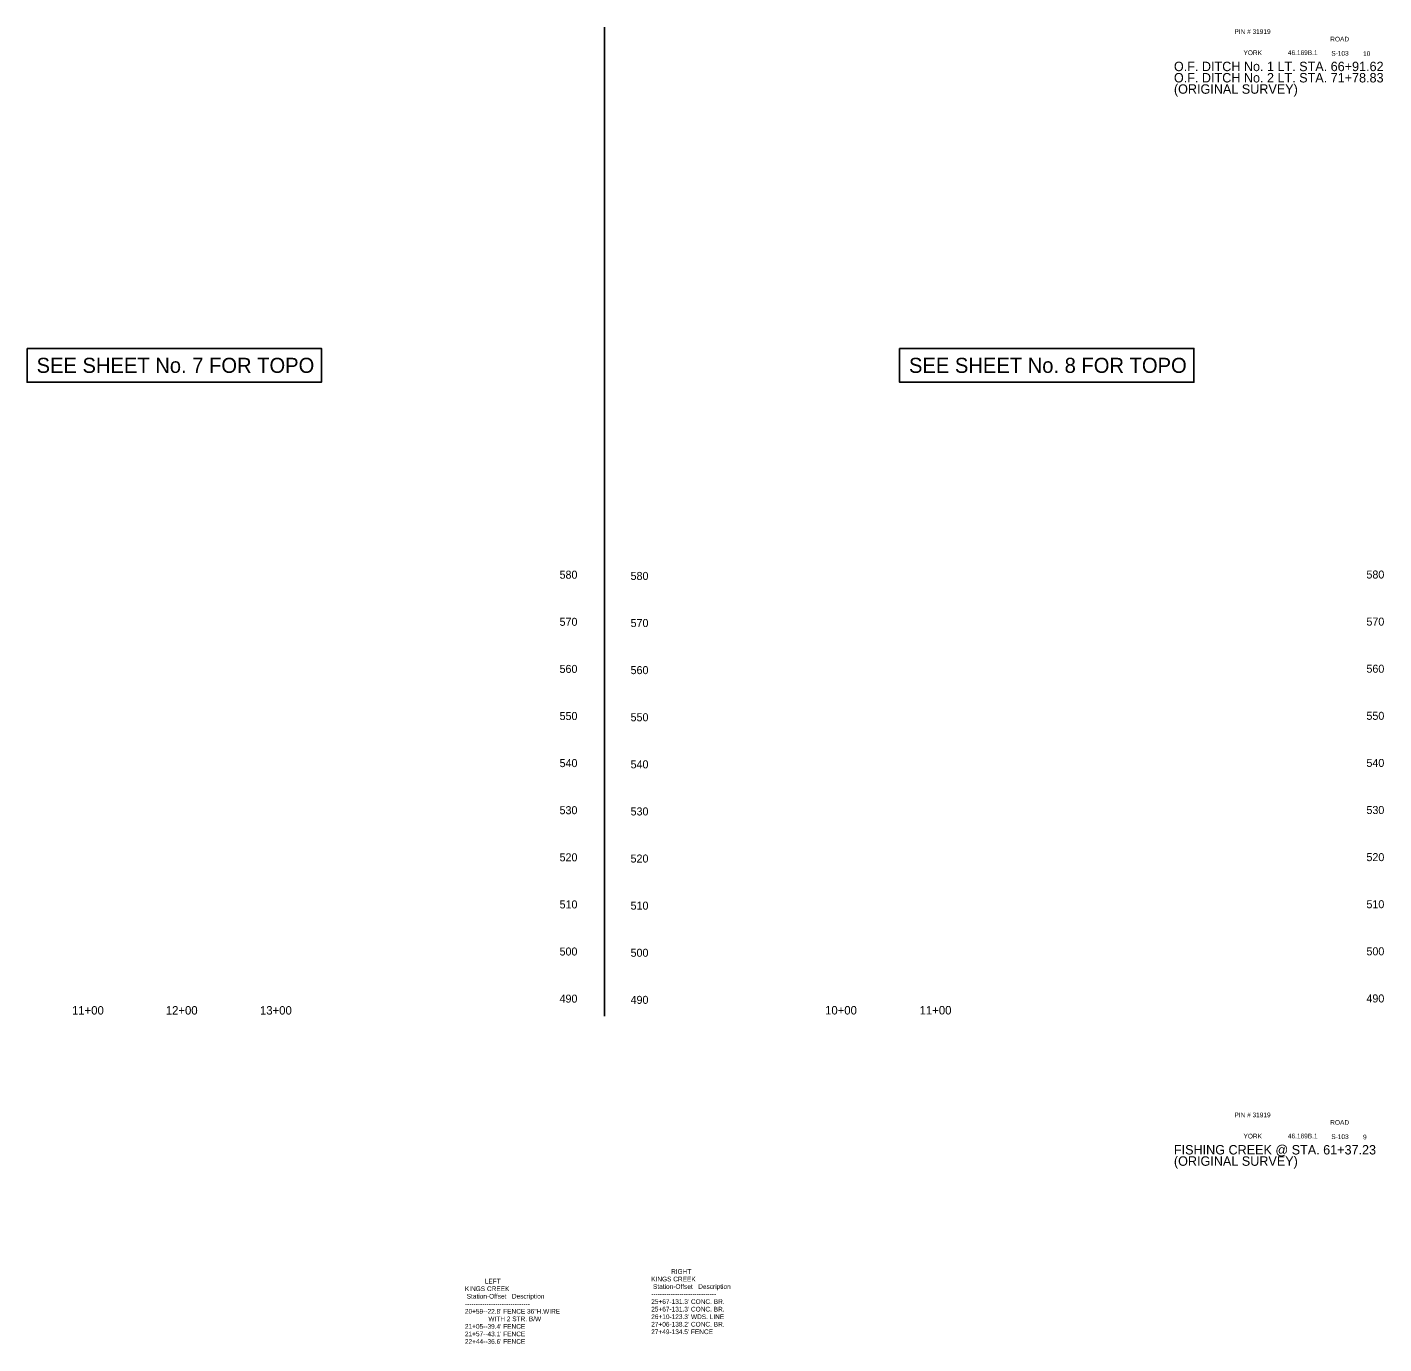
# Model space of a CAD drawing. Extents: x 1959560 to 1962161, y 1107485 to 1113134.
# Drawn here: x 1960721 to 1962161, y 1111736 to 1113134 of the extents above; entities that cross this region are included whole.
import ezdxf

# ---------------------------------------------------------------- set-up
doc = ezdxf.new("R2010")
doc.units = 0
for name, color, linetype in [('Level 24', 7, 'Continuous'), ('Level 41', 7, 'Continuous'), ('Level 42', 7, 'Continuous')]:
    doc.layers.add(name, color=color, linetype=linetype)

msp = doc.modelspace()

# ---------------------------------------------------------------- linework, layer by layer
at = {"layer": 'Level 41'}
msp.add_line((1961333.7, 1113133.6), (1961333.7, 1112083.6), dxfattribs=at)
for points in [[(1960720.8, 1112792.6), (1961033.3, 1112792.6), (1961033.3, 1112756.6), (1960720.8, 1112756.6)], [(1961647.1, 1112792.6), (1961959.6, 1112792.6), (1961959.6, 1112756.6), (1961647.1, 1112756.6)]]:
    msp.add_lwpolyline(points, close=True, dxfattribs=at)

# ---------------------------------------------------------------- texts
at = {"layer": 'Level 24'}
for s, p in [('           RIGHT        ', (1961383.4, 1111810.2)), ('KINGS CREEK         ', (1961185.6, 1111791.9)), ('           LEFT         ', (1961185.6, 1111799.9)), ('KINGS CREEK         ', (1961383.4, 1111802.2)), (' Station-Offset   Description', (1961383.4, 1111794.2)), (' Station-Offset   Description', (1961185.6, 1111783.9)), ('------------------------------', (1961383.4, 1111786.2)), ("25+67-131.3' CONC. BR.  ", (1961383.4, 1111778.2)), ('------------------------------', (1961185.6, 1111775.9)), ('20+59--22.8\' FENCE 36"H.WIRE', (1961185.6, 1111767.9)), ("25+67-131.3' CONC. BR.  ", (1961383.4, 1111770.2)), ("26+10-123.3' WDS. LINE", (1961383.4, 1111762.2)), ("21+05--39.4' FENCE  ", (1961185.6, 1111751.9)), ('             WITH 2 STR. B/W ', (1961185.6, 1111759.9)), ("27+06-138.2' CONC. BR.  ", (1961383.4, 1111754.2)), ("27+49-134.5' FENCE  ", (1961383.4, 1111746.2)), ("21+57--43.1' FENCE  ", (1961185.6, 1111743.9)), ("22+44--36.6' FENCE  ", (1961185.6, 1111735.9))]:
    msp.add_text(s, height=5, dxfattribs=at).set_placement(p)
at = {"layer": 'Level 41'}
for s, height, p in [('PIN # 31919', 5, (1962002.7, 1113126.4)), ('ROAD', 5, (1962104.4, 1113118.4)), ('YORK', 5, (1962012.3, 1113103.9)), ('46.169B.1', 5, (1962059.4, 1113104)), ('S-103', 5, (1962105.5, 1113103.3)), ('10', 5, (1962139.2, 1113102.9)), ('O.F. DITCH No. 1 LT. STA. 66+91.62', 10, (1961938.4, 1113086.9)), ('O.F. DITCH No. 2 LT. STA. 71+78.83', 10, (1961938.4, 1113074.9)), ('(ORIGINAL SURVEY)', 10, (1961938.4, 1113062.9)), ('SEE SHEET No. 7 FOR TOPO', 16, (1960730.8, 1112766.6)), ('SEE SHEET No. 8 FOR TOPO', 16, (1961657.1, 1112766.6)), ('PIN # 31919', 5, (1962002.7, 1111976.4)), ('ROAD', 5, (1962104.4, 1111968.4)), ('YORK', 5, (1962012.3, 1111953.9)), ('46.169B.1', 5, (1962059.4, 1111954)), ('S-103', 5, (1962105.5, 1111953.3)), ('9', 5, (1962139.2, 1111952.9)), ('FISHING CREEK @ STA. 61+37.23', 10, (1961938.4, 1111936.9)), ('(ORIGINAL SURVEY)', 10, (1961938.4, 1111924.9))]:
    msp.add_text(s, height=height, dxfattribs=at).set_placement(p)
at = {"layer": 'Level 42'}
for s, height, p in [('580', 8.5, (1961286.1, 1112548.1)), ('580', 8.5, (1961361.5, 1112546.8)), ('580', 8.5, (1962142.8, 1112548.3)), ('570', 8.5, (1961286.1, 1112498.1)), ('570', 8.5, (1961361.5, 1112496.8)), ('570', 8.5, (1962142.8, 1112498.3)), ('560', 8.5, (1962142.8, 1112448.3)), ('560', 8.5, (1961286.1, 1112448.1)), ('560', 8.5, (1961361.5, 1112446.8)), ('550', 8.5, (1961286.1, 1112398.1)), ('550', 8.5, (1961361.5, 1112396.8)), ('550', 8.5, (1962142.8, 1112398.3)), ('540', 8.5, (1961286.1, 1112348.1)), ('540', 8.5, (1962142.8, 1112348.3)), ('540', 8.5, (1961361.5, 1112346.8)), ('530', 8.5, (1961286.1, 1112298.1)), ('530', 8.5, (1961361.5, 1112296.8)), ('530', 8.5, (1962142.8, 1112298.3)), ('520', 8.5, (1961286.1, 1112248.1)), ('520', 8.5, (1961361.5, 1112246.8)), ('520', 8.5, (1962142.8, 1112248.3)), ('510', 8.5, (1961286.1, 1112198.1)), ('510', 8.5, (1961361.5, 1112196.8)), ('510', 8.5, (1962142.8, 1112198.3)), ('500', 8.5, (1961286.1, 1112148.1)), ('500', 8.5, (1961361.5, 1112146.8)), ('500', 8.5, (1962142.8, 1112148.3)), ('490', 8.5, (1961286.1, 1112098.1)), ('490', 8.5, (1961361.5, 1112096.8)), ('490', 8.5, (1962142.8, 1112098.3)), ('11+00', 9, (1960768.4, 1112085.4)), ('12+00', 9, (1960868, 1112085.4)), ('13+00', 9, (1960968, 1112085.4)), ('10+00', 9, (1961568, 1112085.5)), ('11+00', 9, (1961668.4, 1112085.5))]:
    msp.add_text(s, height=height, dxfattribs=at).set_placement(p)

doc.saveas('drawing.dxf')
